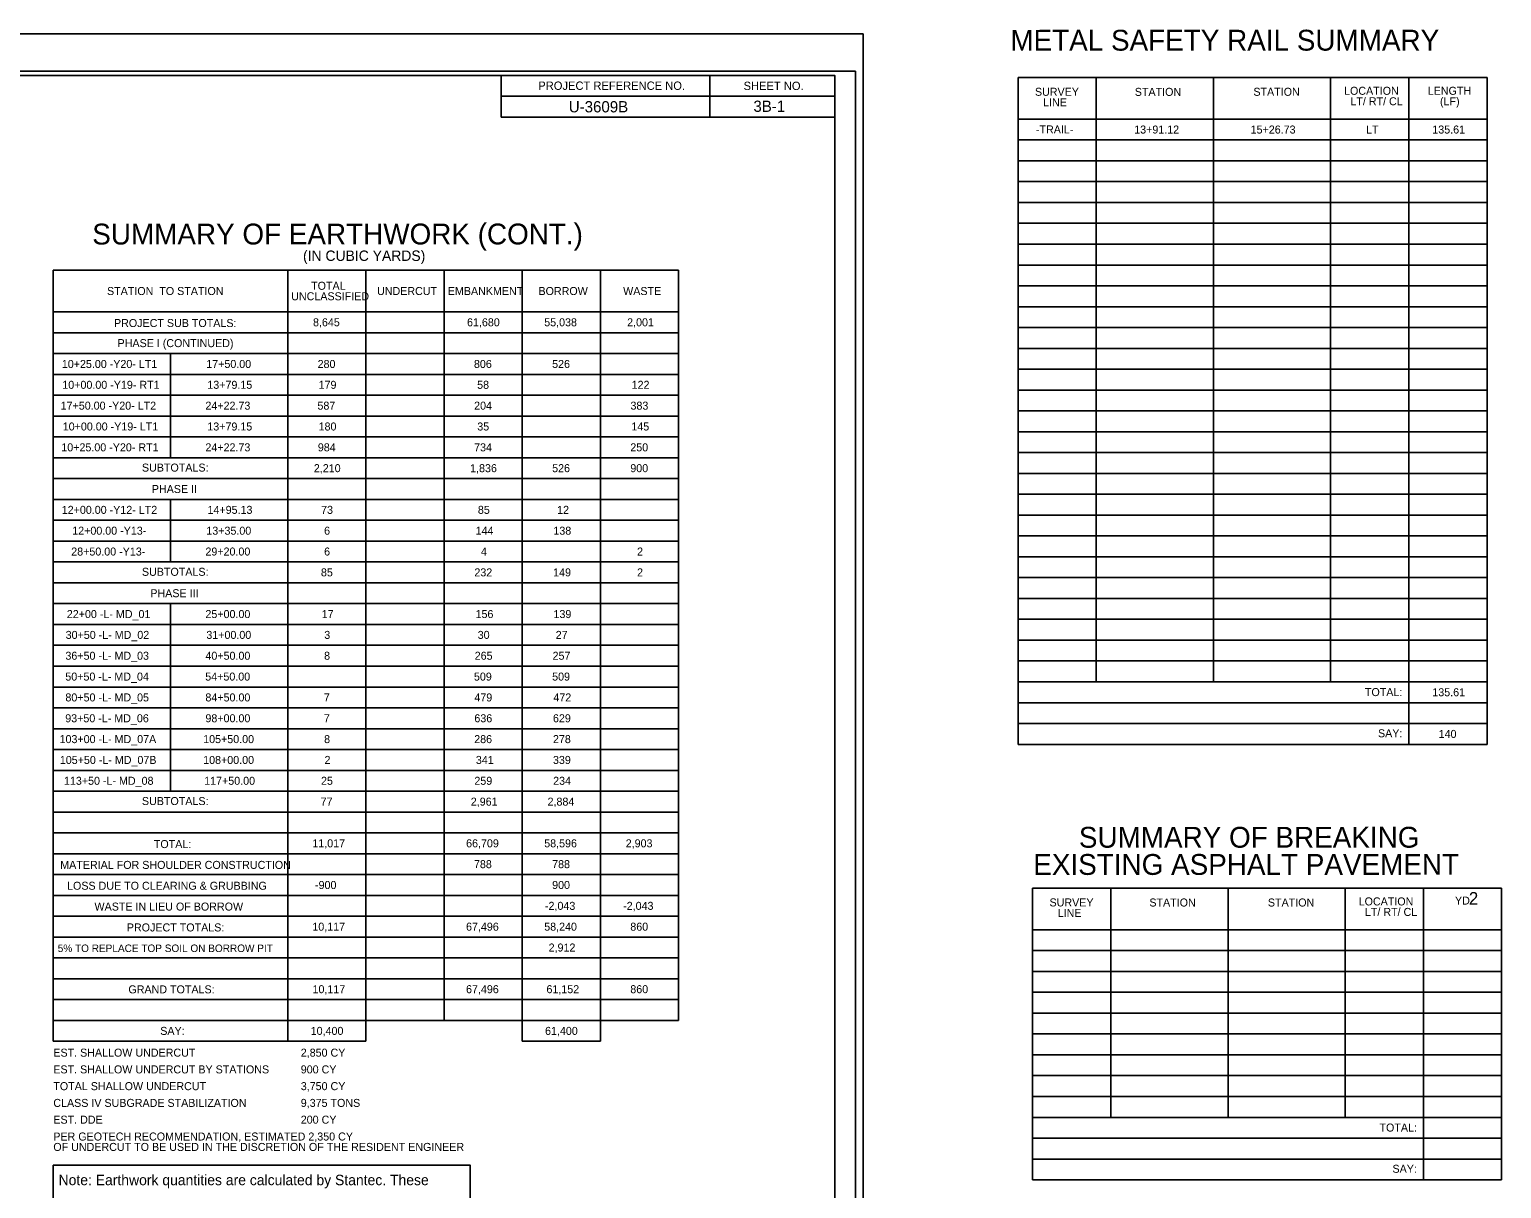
# Model space of a CAD drawing. Extents: x 1729984.8 to 1730033.5, y 539934.2 to 539956.2.
# Drawn here: x 1730015.88 to 1730033.54, y 539942.32 to 539956.22 of the extents above; entities that cross this region are included whole.
import ezdxf

# ---------------------------------------------------------------- set-up
doc = ezdxf.new("R2010")
doc.units = 0
for name, color, linetype in [('Sheet Cutting Line CELL', 7, 'Continuous'), ('Sheet Data Field CELL', 7, 'Continuous'), ('Sheet Plot Border Inside CELL', 7, 'Continuous'), ('Sheet Plot Border Outside CELL', 7, 'Continuous'), ('Sheet Summary Combination CELL', 7, 'Continuous'), ('Sheet Summary Combination Grid CELL', 7, 'Continuous'), ('Sheet Summary Earthwork CELL', 7, 'Continuous')]:
    doc.layers.add(name, color=color, linetype=linetype)

msp = doc.modelspace()

# ---------------------------------------------------------------- linework, layer by layer
at = {"layer": 'Sheet Cutting Line CELL'}
msp.add_line((1730025.883, 539956.171), (1729992.203, 539956.171), dxfattribs=at)
at = {"layer": 'Sheet Plot Border Inside CELL'}
msp.add_lwpolyline([(1730025.793, 539955.722), (1729992.463, 539955.722), (1729992.463, 539934.62), (1730025.793, 539934.62)], close=True, dxfattribs=at)
at = {"layer": 'Sheet Plot Border Outside CELL'}
msp.add_lwpolyline([(1730025.883, 539956.171), (1729992.203, 539956.171), (1729992.203, 539934.171), (1730025.883, 539934.171)], close=True, dxfattribs=at)
at = {"layer": 'Sheet Summary Combination CELL'}
for p, q in [((1730024.043, 539955.67), (1730024.043, 539955.17)), ((1730030.567, 539955.645), (1730030.567, 539955.645)), ((1730030.692, 539955.643), (1730030.692, 539955.643)), ((1730030.873, 539955.647), (1730030.873, 539955.647)), ((1730030.985, 539955.645), (1730030.985, 539955.645)), ((1730021.542, 539955.42), (1730025.543, 539955.42)), ((1730021.542, 539955.17), (1730025.543, 539955.17)), ((1730018.054, 539953.333), (1730018.054, 539953.333)), ((1730018.179, 539953.331), (1730018.179, 539953.331)), ((1730018.36, 539953.335), (1730018.36, 539953.335)), ((1730018.472, 539953.333), (1730018.472, 539953.333)), ((1730030.742, 539945.921), (1730030.742, 539945.921)), ((1730030.867, 539945.919), (1730030.867, 539945.919)), ((1730031.048, 539945.923), (1730031.048, 539945.923)), ((1730031.16, 539945.921), (1730031.16, 539945.921))]:
    msp.add_line(p, q, dxfattribs=at)
for points in [[(1730025.543, 539955.671), (1729995.543, 539955.671), (1729995.543, 539934.671), (1730025.543, 539934.671)], [(1730021.542, 539955.671), (1730025.543, 539955.671), (1730025.543, 539955.17), (1730021.542, 539955.17)]]:
    msp.add_lwpolyline(points, close=True, dxfattribs=at)
at = {"layer": 'Sheet Summary Combination Grid CELL'}
for p, q in [((1730027.742, 539955.646), (1730033.369, 539955.646)), ((1730027.742, 539955.646), (1730027.742, 539947.646)), ((1730028.68, 539955.646), (1730028.68, 539948.396)), ((1730030.087, 539955.646), (1730030.087, 539948.396)), ((1730031.493, 539955.646), (1730031.493, 539948.396)), ((1730032.431, 539955.646), (1730032.431, 539947.646)), ((1730033.369, 539955.646), (1730033.369, 539947.646)), ((1730027.742, 539955.146), (1730033.369, 539955.146)), ((1730027.742, 539954.896), (1730033.369, 539954.896)), ((1730027.742, 539954.646), (1730033.369, 539954.646)), ((1730027.742, 539954.396), (1730033.369, 539954.396)), ((1730027.742, 539954.146), (1730033.369, 539954.146)), ((1730027.742, 539953.896), (1730033.369, 539953.896)), ((1730027.742, 539953.646), (1730033.369, 539953.646)), ((1730016.167, 539953.334), (1730016.167, 539944.084)), ((1730016.167, 539953.334), (1730023.67, 539953.334)), ((1730018.98, 539953.334), (1730018.98, 539944.084)), ((1730019.918, 539953.334), (1730019.918, 539944.084)), ((1730020.856, 539953.334), (1730020.856, 539944.334)), ((1730021.794, 539953.334), (1730021.794, 539944.084)), ((1730022.732, 539953.334), (1730022.732, 539944.084)), ((1730023.67, 539953.334), (1730023.67, 539944.334)), ((1730027.742, 539953.396), (1730033.369, 539953.396)), ((1730027.742, 539953.146), (1730033.369, 539953.146)), ((1730016.167, 539952.834), (1730023.67, 539952.834)), ((1730027.742, 539952.896), (1730033.369, 539952.896)), ((1730027.742, 539952.646), (1730033.369, 539952.646)), ((1730016.167, 539952.584), (1730023.67, 539952.584)), ((1730016.167, 539952.334), (1730023.67, 539952.334)), ((1730017.574, 539952.334), (1730017.574, 539951.084)), ((1730027.742, 539952.396), (1730033.369, 539952.396)), ((1730016.167, 539952.084), (1730023.67, 539952.084)), ((1730027.742, 539952.146), (1730033.369, 539952.146)), ((1730027.742, 539951.896), (1730033.369, 539951.896)), ((1730016.167, 539951.834), (1730023.67, 539951.834)), ((1730016.167, 539951.584), (1730023.67, 539951.584)), ((1730027.742, 539951.646), (1730033.369, 539951.646)), ((1730027.742, 539951.396), (1730033.369, 539951.396)), ((1730016.167, 539951.334), (1730023.67, 539951.334)), ((1730016.167, 539951.084), (1730023.67, 539951.084)), ((1730027.742, 539951.146), (1730033.369, 539951.146)), ((1730016.167, 539950.834), (1730023.67, 539950.834)), ((1730027.742, 539950.896), (1730033.369, 539950.896)), ((1730016.167, 539950.584), (1730023.67, 539950.584)), ((1730017.574, 539950.584), (1730017.574, 539949.834)), ((1730027.742, 539950.646), (1730033.369, 539950.646)), ((1730016.167, 539950.334), (1730023.67, 539950.334)), ((1730027.742, 539950.396), (1730033.369, 539950.396)), ((1730027.742, 539950.146), (1730033.369, 539950.146)), ((1730016.167, 539950.084), (1730023.67, 539950.084)), ((1730016.167, 539949.834), (1730023.67, 539949.834)), ((1730027.742, 539949.896), (1730033.369, 539949.896)), ((1730027.742, 539949.646), (1730033.369, 539949.646)), ((1730016.167, 539949.584), (1730023.67, 539949.584)), ((1730016.167, 539949.334), (1730023.67, 539949.334)), ((1730017.574, 539949.334), (1730017.574, 539947.084)), ((1730027.742, 539949.396), (1730033.369, 539949.396)), ((1730016.167, 539949.084), (1730023.67, 539949.084)), ((1730027.742, 539949.146), (1730033.369, 539949.146)), ((1730027.742, 539948.896), (1730033.369, 539948.896)), ((1730016.167, 539948.834), (1730023.67, 539948.834)), ((1730016.167, 539948.584), (1730023.67, 539948.584)), ((1730027.742, 539948.646), (1730033.369, 539948.646)), ((1730027.742, 539948.396), (1730033.369, 539948.396)), ((1730016.167, 539948.334), (1730023.67, 539948.334)), ((1730016.167, 539948.084), (1730023.67, 539948.084)), ((1730027.742, 539948.146), (1730033.369, 539948.146)), ((1730016.167, 539947.834), (1730023.67, 539947.834)), ((1730027.742, 539947.896), (1730033.369, 539947.896)), ((1730016.167, 539947.584), (1730023.67, 539947.584)), ((1730027.742, 539947.646), (1730033.369, 539947.646)), ((1730016.167, 539947.334), (1730023.67, 539947.334)), ((1730016.167, 539947.084), (1730023.67, 539947.084)), ((1730016.167, 539946.834), (1730023.67, 539946.834)), ((1730016.167, 539946.584), (1730023.67, 539946.584)), ((1730016.167, 539946.334), (1730023.67, 539946.334)), ((1730016.167, 539946.084), (1730023.67, 539946.084)), ((1730027.917, 539945.922), (1730033.544, 539945.922)), ((1730027.917, 539945.922), (1730027.917, 539942.422)), ((1730028.855, 539945.922), (1730028.855, 539943.172)), ((1730030.262, 539945.922), (1730030.262, 539943.172)), ((1730031.668, 539945.922), (1730031.668, 539943.172)), ((1730032.606, 539945.922), (1730032.606, 539942.422)), ((1730033.544, 539945.922), (1730033.544, 539942.422)), ((1730016.167, 539945.834), (1730023.67, 539945.834)), ((1730016.167, 539945.584), (1730023.67, 539945.584)), ((1730027.917, 539945.422), (1730033.544, 539945.422)), ((1730016.167, 539945.334), (1730023.67, 539945.334)), ((1730016.167, 539945.084), (1730023.67, 539945.084)), ((1730027.917, 539945.172), (1730033.544, 539945.172)), ((1730016.167, 539944.834), (1730023.67, 539944.834)), ((1730027.917, 539944.922), (1730033.544, 539944.922)), ((1730027.917, 539944.672), (1730033.544, 539944.672)), ((1730016.167, 539944.584), (1730023.67, 539944.584)), ((1730016.167, 539944.334), (1730023.67, 539944.334)), ((1730027.917, 539944.422), (1730033.544, 539944.422)), ((1730027.917, 539944.172), (1730033.544, 539944.172)), ((1730016.167, 539944.084), (1730019.918, 539944.084)), ((1730021.794, 539944.084), (1730022.732, 539944.084)), ((1730027.917, 539943.922), (1730033.544, 539943.922)), ((1730027.917, 539943.672), (1730033.544, 539943.672)), ((1730027.917, 539943.422), (1730033.544, 539943.422)), ((1730027.917, 539943.172), (1730033.544, 539943.172)), ((1730027.917, 539942.922), (1730033.544, 539942.922)), ((1730027.917, 539942.672), (1730033.544, 539942.672)), ((1730027.917, 539942.422), (1730033.544, 539942.422))]:
    msp.add_line(p, q, dxfattribs=at)
at = {"layer": 'Sheet Summary Earthwork CELL'}
msp.add_lwpolyline([(1730016.167, 539942.6), (1730021.168, 539942.6), (1730021.168, 539941.82), (1730016.167, 539941.82)], close=True, dxfattribs=at)

# ---------------------------------------------------------------- texts
at = {"layer": 'Sheet Data Field CELL'}
for s, p in [('U-3609B', (1730022.352, 539955.227)), ('3B-1', (1730024.567, 539955.233))]:
    msp.add_text(s, height=0.135, dxfattribs=at).set_placement(p)
at = {"layer": 'Sheet Summary Combination CELL'}
for s, p in [('METAL SAFETY RAIL SUMMARY', (1730027.65, 539955.967)), ('SUMMARY OF EARTHWORK (CONT.)', (1730016.634, 539953.642)), ('SUMMARY OF BREAKING', (1730028.472, 539946.406)), ('EXISTING ASPHALT PAVEMENT', (1730027.925, 539946.08))]:
    msp.add_text(s, height=0.25, rotation=0.0119, dxfattribs=at).set_placement(p)
for s, height, p in [('PROJECT REFERENCE NO.', 0.1, (1730021.986, 539955.497)), ('SHEET NO.', 0.1, (1730024.449, 539955.495)), ('SURVEY', 0.096, (1730027.945, 539955.426)), ('STATION', 0.096, (1730029.143, 539955.425)), ('STATION', 0.096, (1730030.566, 539955.426)), ('LOCATION', 0.096, (1730031.654, 539955.438)), ('LINE', 0.096, (1730028.043, 539955.3)), ('LT/ RT/ CL', 0.096, (1730031.73, 539955.312)), ('-TRAIL-', 0.096, (1730027.957, 539954.974)), ('13+91.12', 0.096, (1730029.136, 539954.973)), ('15+26.73', 0.096, (1730030.533, 539954.973)), ('LT', 0.096, (1730031.918, 539954.973)), ('135.61', 0.096, (1730032.713, 539954.973)), ('(IN CUBIC YARDS)', 0.125, (1730019.163, 539953.445)), ('STATION  TO STATION', 0.096, (1730016.811, 539953.036)), ('TOTAL', 0.096, (1730019.26, 539953.099)), ('UNDERCUT', 0.096, (1730020.051, 539953.036)), ('EMBANKMENT', 0.096, (1730020.9, 539953.036)), ('BORROW', 0.096, (1730021.988, 539953.036)), ('WASTE', 0.096, (1730023.004, 539953.036)), ('UNCLASSIFIED', 0.096, (1730019.021, 539952.973)), ('PROJECT SUB TOTALS:', 0.096, (1730016.895, 539952.652)), ('8,645', 0.096, (1730019.283, 539952.661)), ('61,680', 0.096, (1730021.131, 539952.661)), ('55,038', 0.096, (1730022.057, 539952.661)), ('2,001', 0.096, (1730023.052, 539952.661)), ('PHASE I (CONTINUED)', 0.096, (1730016.938, 539952.411)), ('10+25.00 -Y20- LT1', 0.096, (1730016.269, 539952.161)), ('17+50.00', 0.096, (1730018.002, 539952.161)), ('280', 0.096, (1730019.338, 539952.161)), ('806', 0.096, (1730021.214, 539952.161)), ('526', 0.096, (1730022.152, 539952.161)), ('10+00.00 -Y19- RT1', 0.096, (1730016.275, 539951.911)), ('13+79.15', 0.096, (1730018.015, 539951.911)), ('179', 0.096, (1730019.35, 539951.911)), ('58', 0.096, (1730021.252, 539951.911)), ('122', 0.096, (1730023.106, 539951.911)), ('17+50.00 -Y20- LT2', 0.096, (1730016.255, 539951.661)), ('24+22.73', 0.096, (1730017.992, 539951.661)), ('587', 0.096, (1730019.336, 539951.661)), ('204', 0.096, (1730021.216, 539951.661)), ('383', 0.096, (1730023.092, 539951.661)), ('10+00.00 -Y19- LT1', 0.096, (1730016.28, 539951.411)), ('13+79.15', 0.096, (1730018.015, 539951.411)), ('180', 0.096, (1730019.35, 539951.411)), ('35', 0.096, (1730021.254, 539951.411)), ('145', 0.096, (1730023.103, 539951.411)), ('10+25.00 -Y20- RT1', 0.096, (1730016.263, 539951.161)), ('24+22.73', 0.096, (1730017.992, 539951.161)), ('984', 0.096, (1730019.341, 539951.161)), ('734', 0.096, (1730021.216, 539951.161)), ('250', 0.096, (1730023.09, 539951.161)), ('SUBTOTALS:', 0.096, (1730017.23, 539950.918)), ('2,210', 0.096, (1730019.293, 539950.911)), ('1,836', 0.096, (1730021.168, 539950.911)), ('526', 0.096, (1730022.152, 539950.911)), ('900', 0.096, (1730023.09, 539950.911)), ('PHASE II', 0.096, (1730017.349, 539950.661)), ('12+00.00 -Y12- LT2', 0.096, (1730016.268, 539950.411)), ('14+95.13', 0.096, (1730018.017, 539950.411)), ('73', 0.096, (1730019.38, 539950.411)), ('85', 0.096, (1730021.261, 539950.411)), ('12', 0.096, (1730022.212, 539950.411)), ('12+00.00 -Y13-', 0.096, (1730016.394, 539950.161)), ('13+35.00', 0.096, (1730018.003, 539950.161)), ('6', 0.096, (1730019.416, 539950.161)), ('144', 0.096, (1730021.234, 539950.161)), ('138', 0.096, (1730022.167, 539950.161)), ('28+50.00 -Y13-', 0.096, (1730016.382, 539949.911)), ('29+20.00', 0.096, (1730017.992, 539949.911)), ('6', 0.096, (1730019.416, 539949.911)), ('4', 0.096, (1730021.298, 539949.911)), ('2', 0.096, (1730023.171, 539949.911)), ('SUBTOTALS:', 0.096, (1730017.23, 539949.668)), ('85', 0.096, (1730019.378, 539949.661)), ('232', 0.096, (1730021.219, 539949.661)), ('149', 0.096, (1730022.164, 539949.661)), ('2', 0.096, (1730023.171, 539949.661)), ('PHASE III', 0.096, (1730017.331, 539949.411)), ('22+00 -L- MD_01', 0.096, (1730016.329, 539949.161)), ('25+00.00', 0.096, (1730017.992, 539949.161)), ('17', 0.096, (1730019.387, 539949.161)), ('156', 0.096, (1730021.233, 539949.161)), ('139', 0.096, (1730022.168, 539949.161)), ('30+50 -L- MD_02', 0.096, (1730016.315, 539948.911)), ('31+00.00', 0.096, (1730018.003, 539948.911)), ('3', 0.096, (1730019.418, 539948.911)), ('30', 0.096, (1730021.259, 539948.911)), ('27', 0.096, (1730022.195, 539948.911)), ('36+50 -L- MD_03', 0.096, (1730016.312, 539948.661)), ('40+50.00', 0.096, (1730017.992, 539948.661)), ('8', 0.096, (1730019.416, 539948.661)), ('265', 0.096, (1730021.223, 539948.661)), ('257', 0.096, (1730022.157, 539948.661)), ('50+50 -L- MD_04', 0.096, (1730016.311, 539948.411)), ('54+50.00', 0.096, (1730017.99, 539948.411)), ('509', 0.096, (1730021.214, 539948.411)), ('509', 0.096, (1730022.152, 539948.411)), ('80+50 -L- MD_05', 0.096, (1730016.312, 539948.161)), ('84+50.00', 0.096, (1730017.992, 539948.161)), ('7', 0.096, (1730019.413, 539948.161)), ('479', 0.096, (1730021.219, 539948.161)), ('472', 0.096, (1730022.167, 539948.161)), ('TOTAL:', 0.096, (1730031.904, 539948.225)), ('135.61', 0.096, (1730032.713, 539948.223)), ('93+50 -L- MD_06', 0.096, (1730016.31, 539947.911)), ('98+00.00', 0.096, (1730017.992, 539947.911)), ('7', 0.096, (1730019.413, 539947.911)), ('636', 0.096, (1730021.219, 539947.911)), ('629', 0.096, (1730022.162, 539947.911)), ('SAY:', 0.096, (1730032.061, 539947.731)), ('103+00 -L- MD_07A', 0.096, (1730016.242, 539947.661)), ('105+50.00', 0.096, (1730017.965, 539947.661)), ('8', 0.096, (1730019.416, 539947.661)), ('286', 0.096, (1730021.217, 539947.661)), ('278', 0.096, (1730022.162, 539947.661)), ('140', 0.096, (1730032.789, 539947.723)), ('105+50 -L- MD_07B', 0.096, (1730016.245, 539947.411)), ('108+00.00', 0.096, (1730017.965, 539947.411)), ('2', 0.096, (1730019.421, 539947.411)), ('341', 0.096, (1730021.237, 539947.411)), ('339', 0.096, (1730022.162, 539947.411)), ('113+50 -L- MD_08', 0.096, (1730016.295, 539947.161)), ('117+50.00', 0.096, (1730017.977, 539947.161)), ('25', 0.096, (1730019.379, 539947.161)), ('259', 0.096, (1730021.219, 539947.161)), ('234', 0.096, (1730022.164, 539947.161)), ('SUBTOTALS:', 0.096, (1730017.23, 539946.918)), ('77', 0.096, (1730019.374, 539946.911)), ('2,961', 0.096, (1730021.176, 539946.911)), ('2,884', 0.096, (1730022.097, 539946.911)), ('TOTAL:', 0.096, (1730017.373, 539946.402)), ('11,017', 0.096, (1730019.275, 539946.411)), ('66,709', 0.096, (1730021.12, 539946.411)), ('58,596', 0.096, (1730022.057, 539946.411)), ('2,903', 0.096, (1730023.035, 539946.411)), ('MATERIAL FOR SHOULDER CONSTRUCTION', 0.096, (1730016.25, 539946.152)), ('788', 0.096, (1730021.214, 539946.161)), ('788', 0.096, (1730022.152, 539946.161)), ('LOSS DUE TO CLEARING & GRUBBING', 0.096, (1730016.332, 539945.902)), ('-900', 0.096, (1730019.307, 539945.911)), ('900', 0.096, (1730022.152, 539945.911)), ('WASTE IN LIEU OF BORROW', 0.096, (1730016.661, 539945.652)), ('-2,043', 0.096, (1730022.066, 539945.661)), ('-2,043', 0.096, (1730023.004, 539945.661)), ('SURVEY', 0.096, (1730028.12, 539945.702)), ('STATION', 0.096, (1730029.318, 539945.701)), ('STATION', 0.096, (1730030.74, 539945.701)), ('LOCATION', 0.096, (1730031.829, 539945.714)), ('LINE', 0.096, (1730028.218, 539945.576)), ('LT/ RT/ CL', 0.096, (1730031.904, 539945.588)), ('PROJECT TOTALS:', 0.096, (1730017.049, 539945.402)), ('10,117', 0.096, (1730019.275, 539945.411)), ('67,496', 0.096, (1730021.119, 539945.411)), ('58,240', 0.096, (1730022.057, 539945.411)), ('860', 0.096, (1730023.09, 539945.411)), ('5% TO REPLACE TOP SOIL ON BORROW PIT', 0.09, (1730016.22, 539945.155)), ('2,912', 0.096, (1730022.11, 539945.161)), ('GRAND TOTALS:', 0.096, (1730017.068, 539944.659)), ('10,117', 0.096, (1730019.277, 539944.661)), ('67,496', 0.096, (1730021.119, 539944.661)), ('61,152', 0.096, (1730022.084, 539944.661)), ('860', 0.096, (1730023.09, 539944.661)), ('SAY:', 0.096, (1730017.45, 539944.161)), ('10,400', 0.096, (1730019.255, 539944.161)), ('61,400', 0.096, (1730022.067, 539944.161)), ('EST. SHALLOW UNDERCUT', 0.096, (1730016.167, 539943.9)), ('2,850 CY', 0.096, (1730019.136, 539943.9)), ('EST. SHALLOW UNDERCUT BY STATIONS', 0.096, (1730016.167, 539943.699)), ('900 CY', 0.096, (1730019.136, 539943.699)), ('TOTAL SHALLOW UNDERCUT', 0.096, (1730016.167, 539943.498)), ('3,750 CY', 0.096, (1730019.136, 539943.498)), ('CLASS IV SUBGRADE STABILIZATION', 0.096, (1730016.167, 539943.297)), ('9,375 TONS', 0.096, (1730019.136, 539943.297)), ('EST. DDE', 0.096, (1730016.167, 539943.096)), ('200 CY', 0.096, (1730019.136, 539943.096)), ('TOTAL:', 0.096, (1730032.079, 539943.001)), ('PER GEOTECH RECOMMENDATION, ESTIMATED 2,350 CY', 0.096, (1730016.167, 539942.894)), ('OF UNDERCUT TO BE USED IN THE DISCRETION OF THE RESIDENT ENGINEER', 0.096, (1730016.167, 539942.769)), ('SAY:', 0.096, (1730032.235, 539942.507))]:
    msp.add_text(s, height=height, dxfattribs=at).set_placement(p)
at = {"layer": 'Sheet Summary Combination Grid CELL'}
for s, height, p in [('LENGTH', 0.096, (1730032.658, 539955.438)), ('(LF)', 0.096, (1730032.805, 539955.312)), ('YD', 0.096, (1730032.985, 539945.724)), ('2', 0.15, (1730033.152, 539945.724))]:
    msp.add_text(s, height=height, dxfattribs=at).set_placement(p)
at = {"layer": 'Sheet Summary Earthwork CELL'}
msp.add_text('Note: Earthwork quantities are calculated by Stantec. These', height=0.125, dxfattribs=at).set_placement((1730016.23, 539942.358))

doc.saveas('drawing.dxf')
